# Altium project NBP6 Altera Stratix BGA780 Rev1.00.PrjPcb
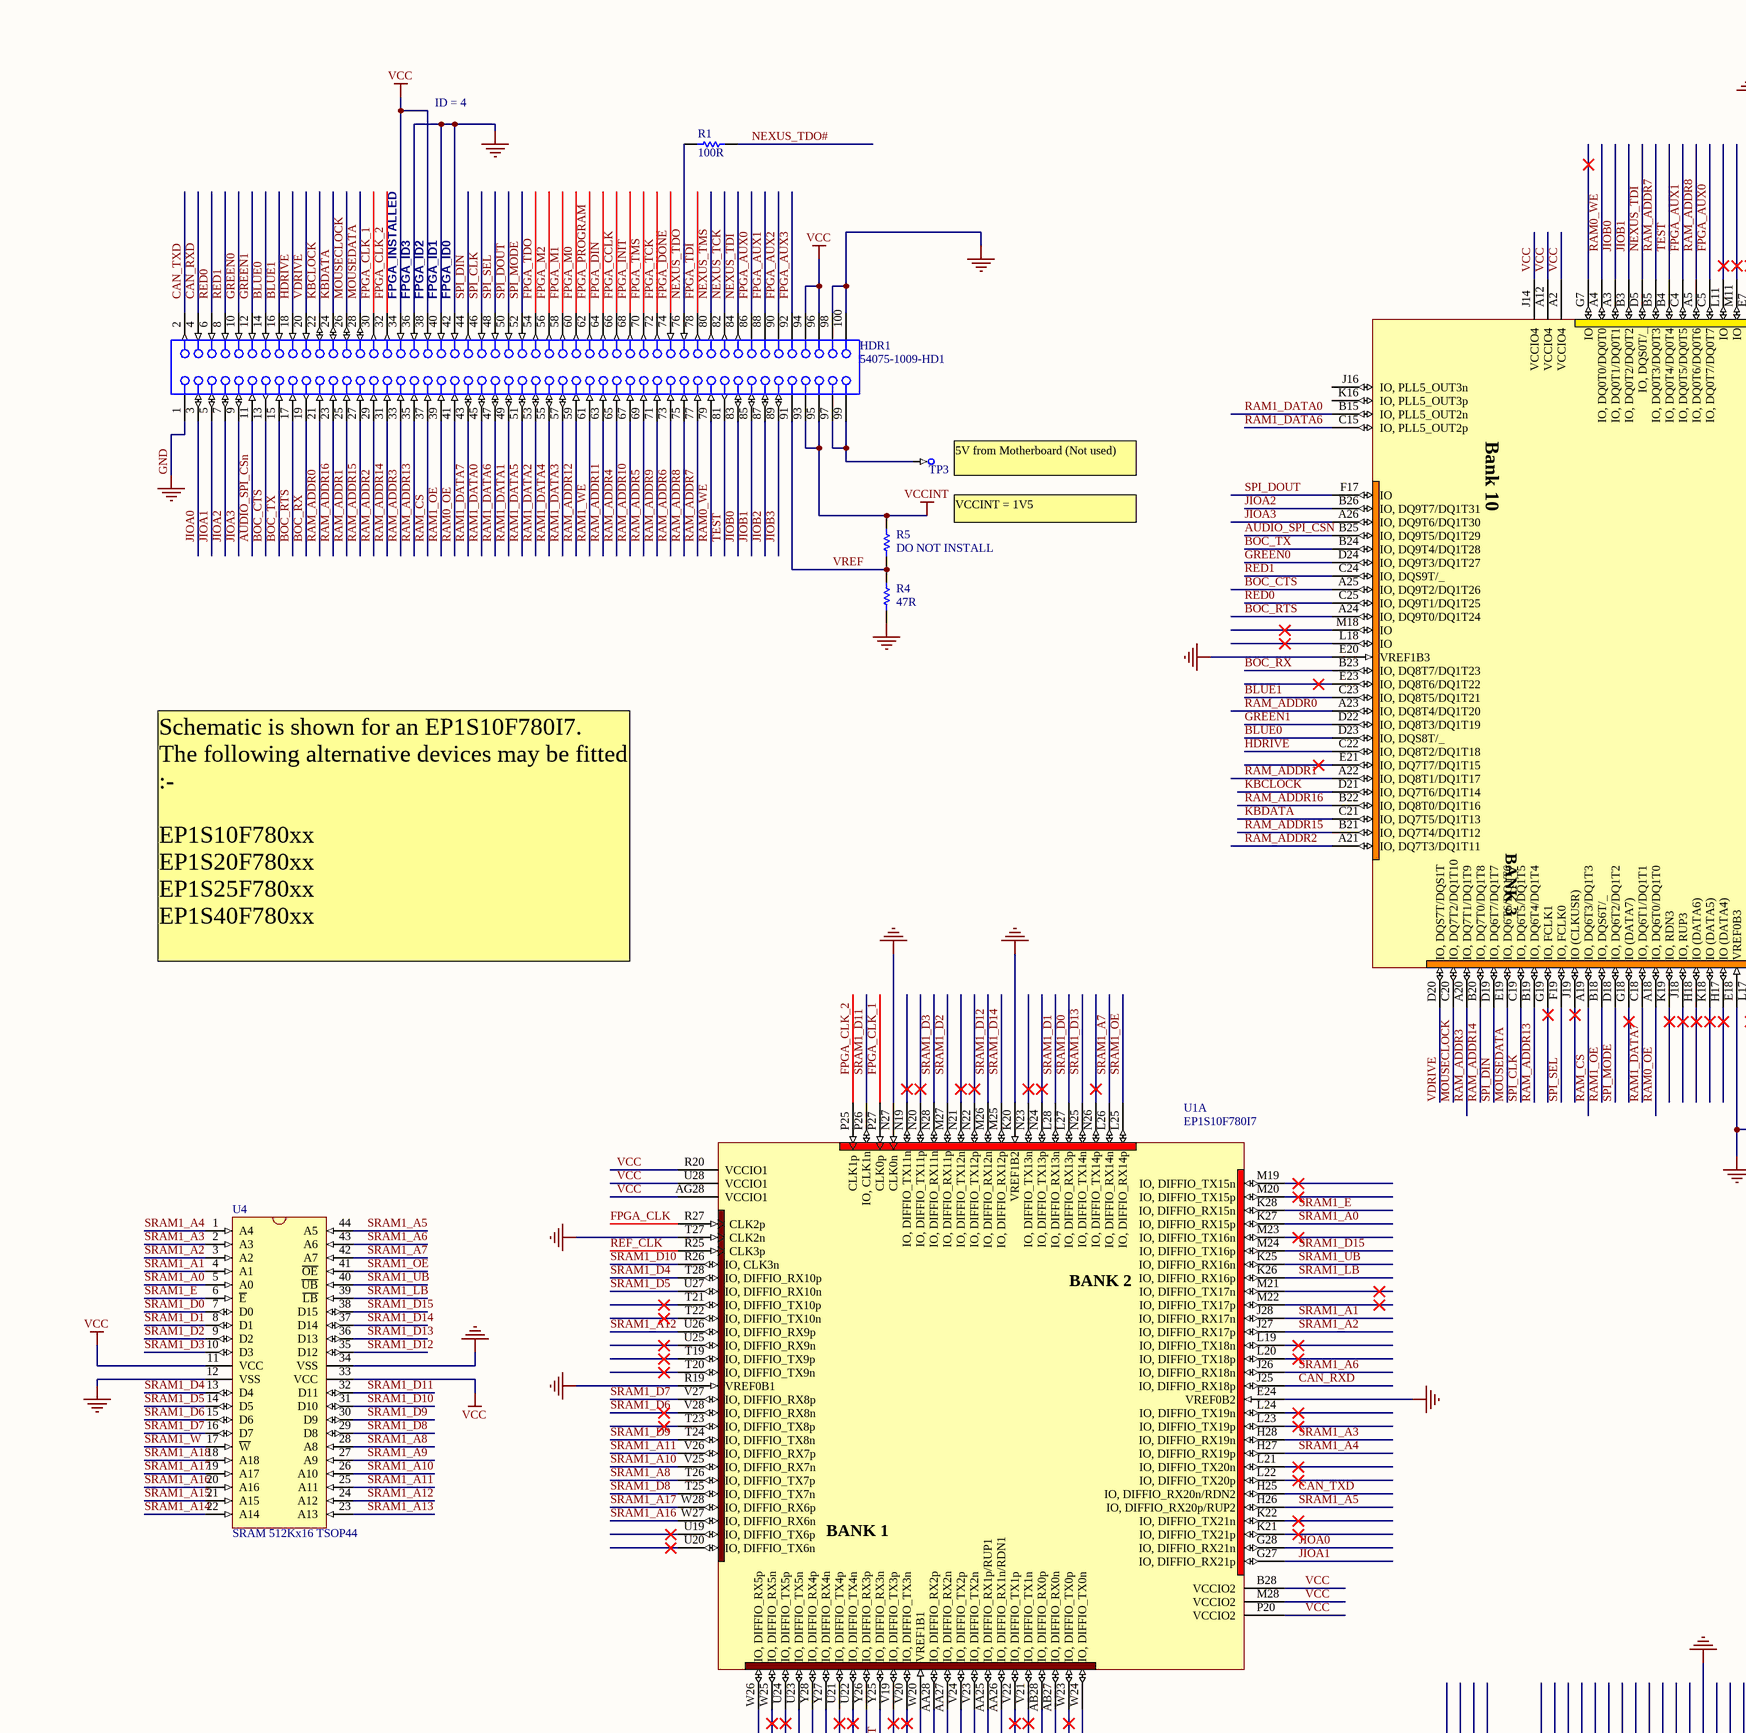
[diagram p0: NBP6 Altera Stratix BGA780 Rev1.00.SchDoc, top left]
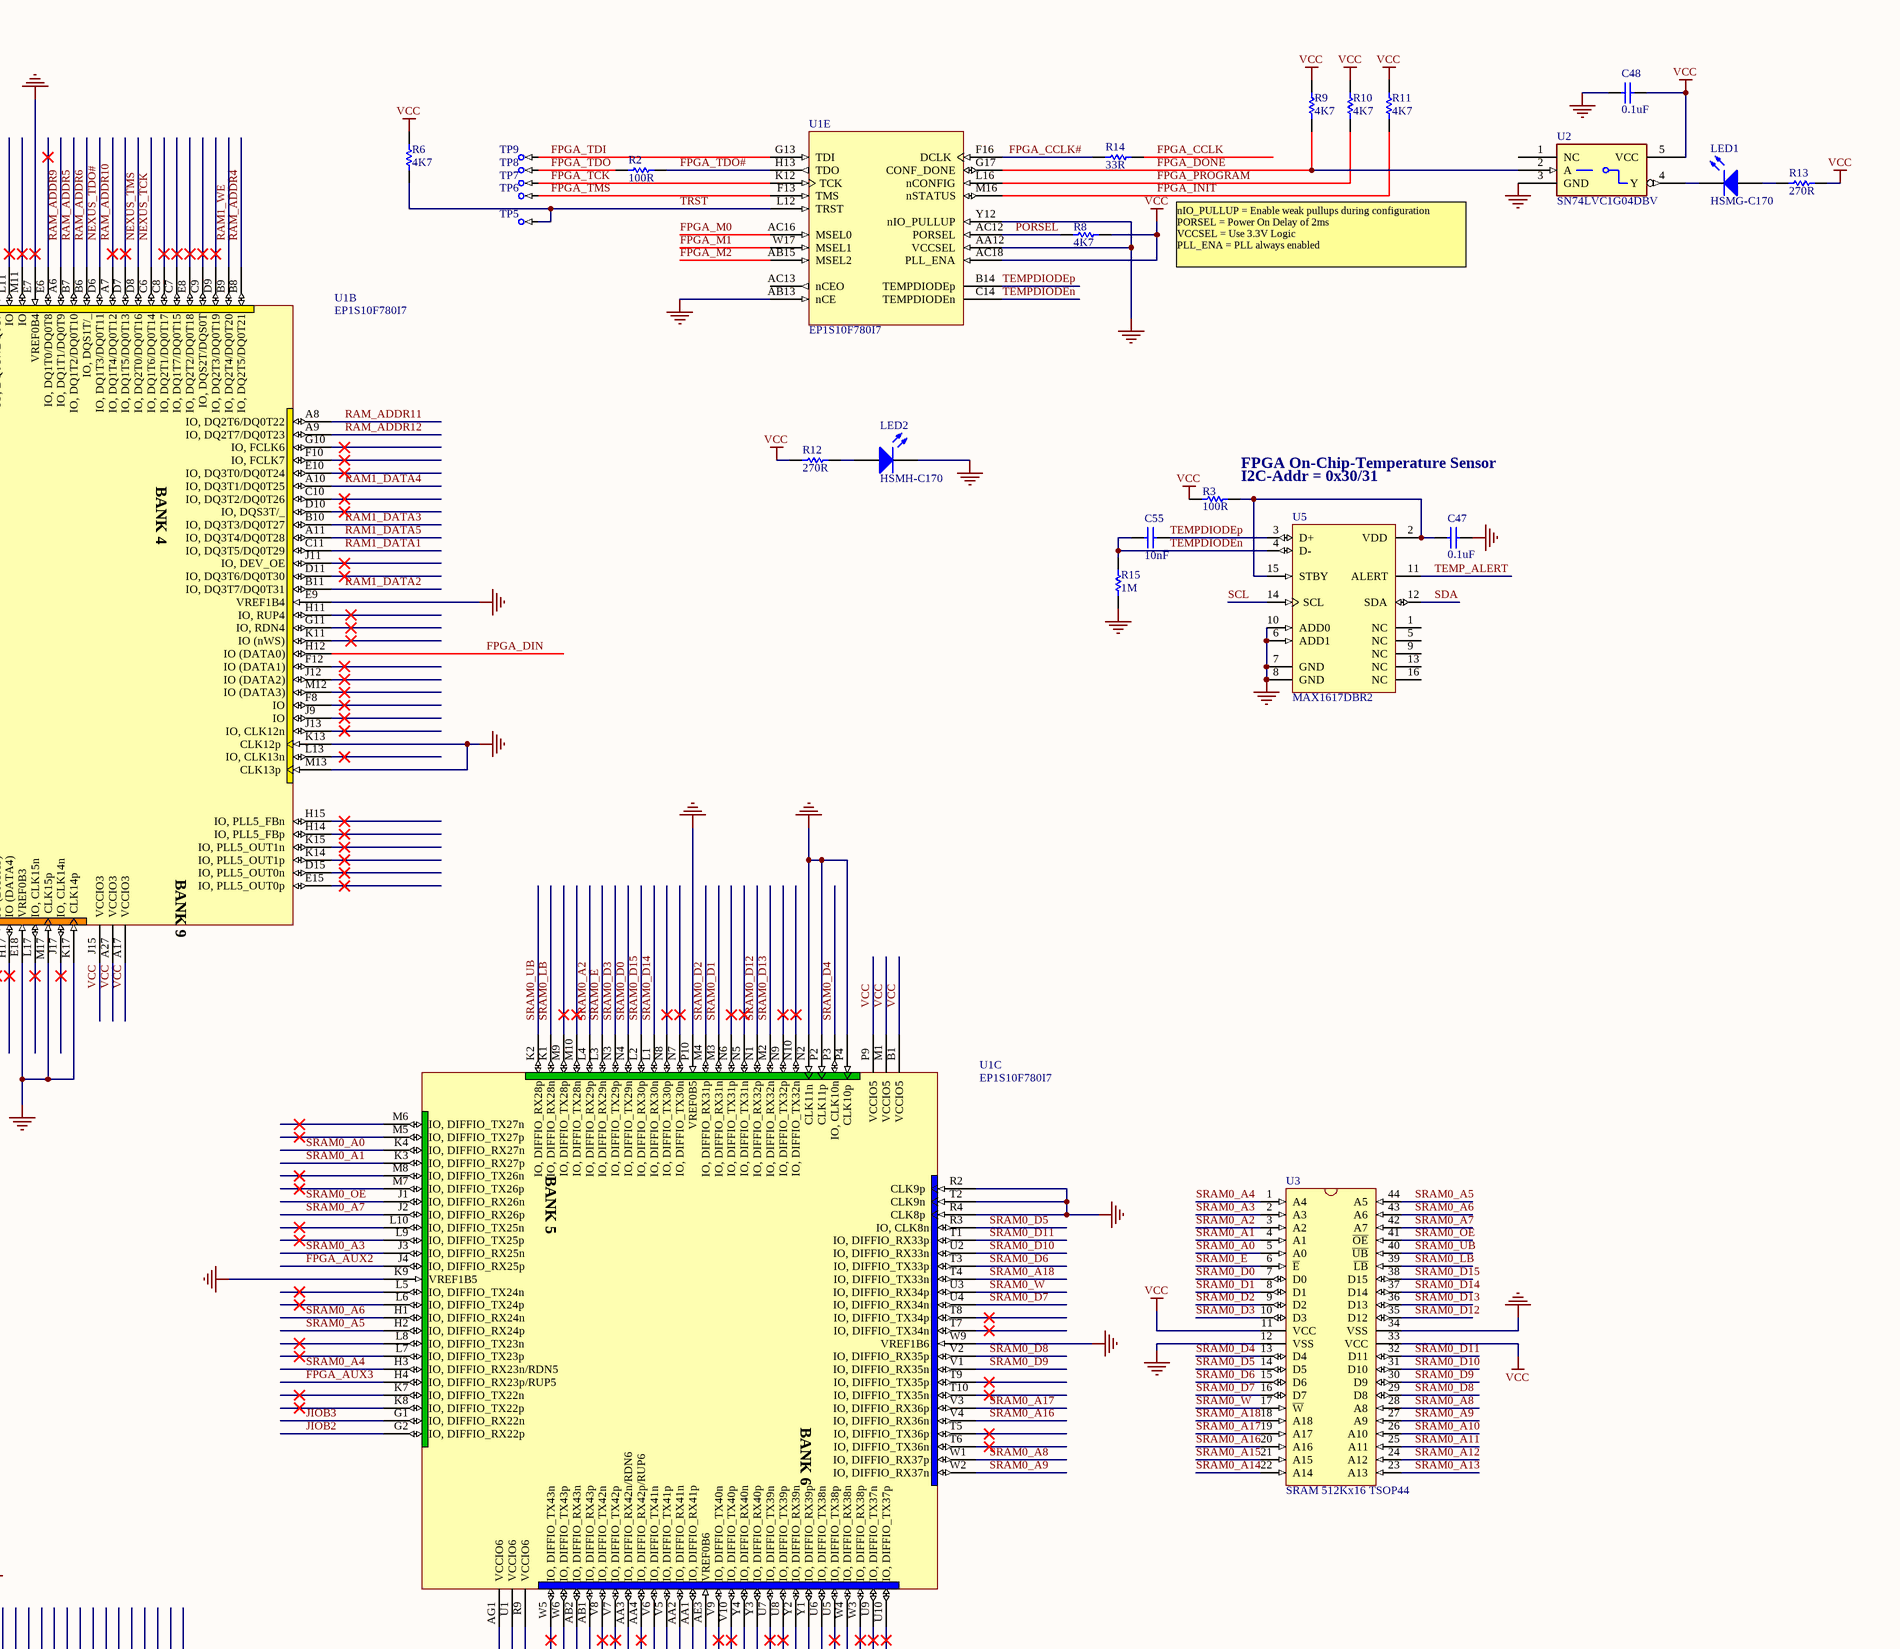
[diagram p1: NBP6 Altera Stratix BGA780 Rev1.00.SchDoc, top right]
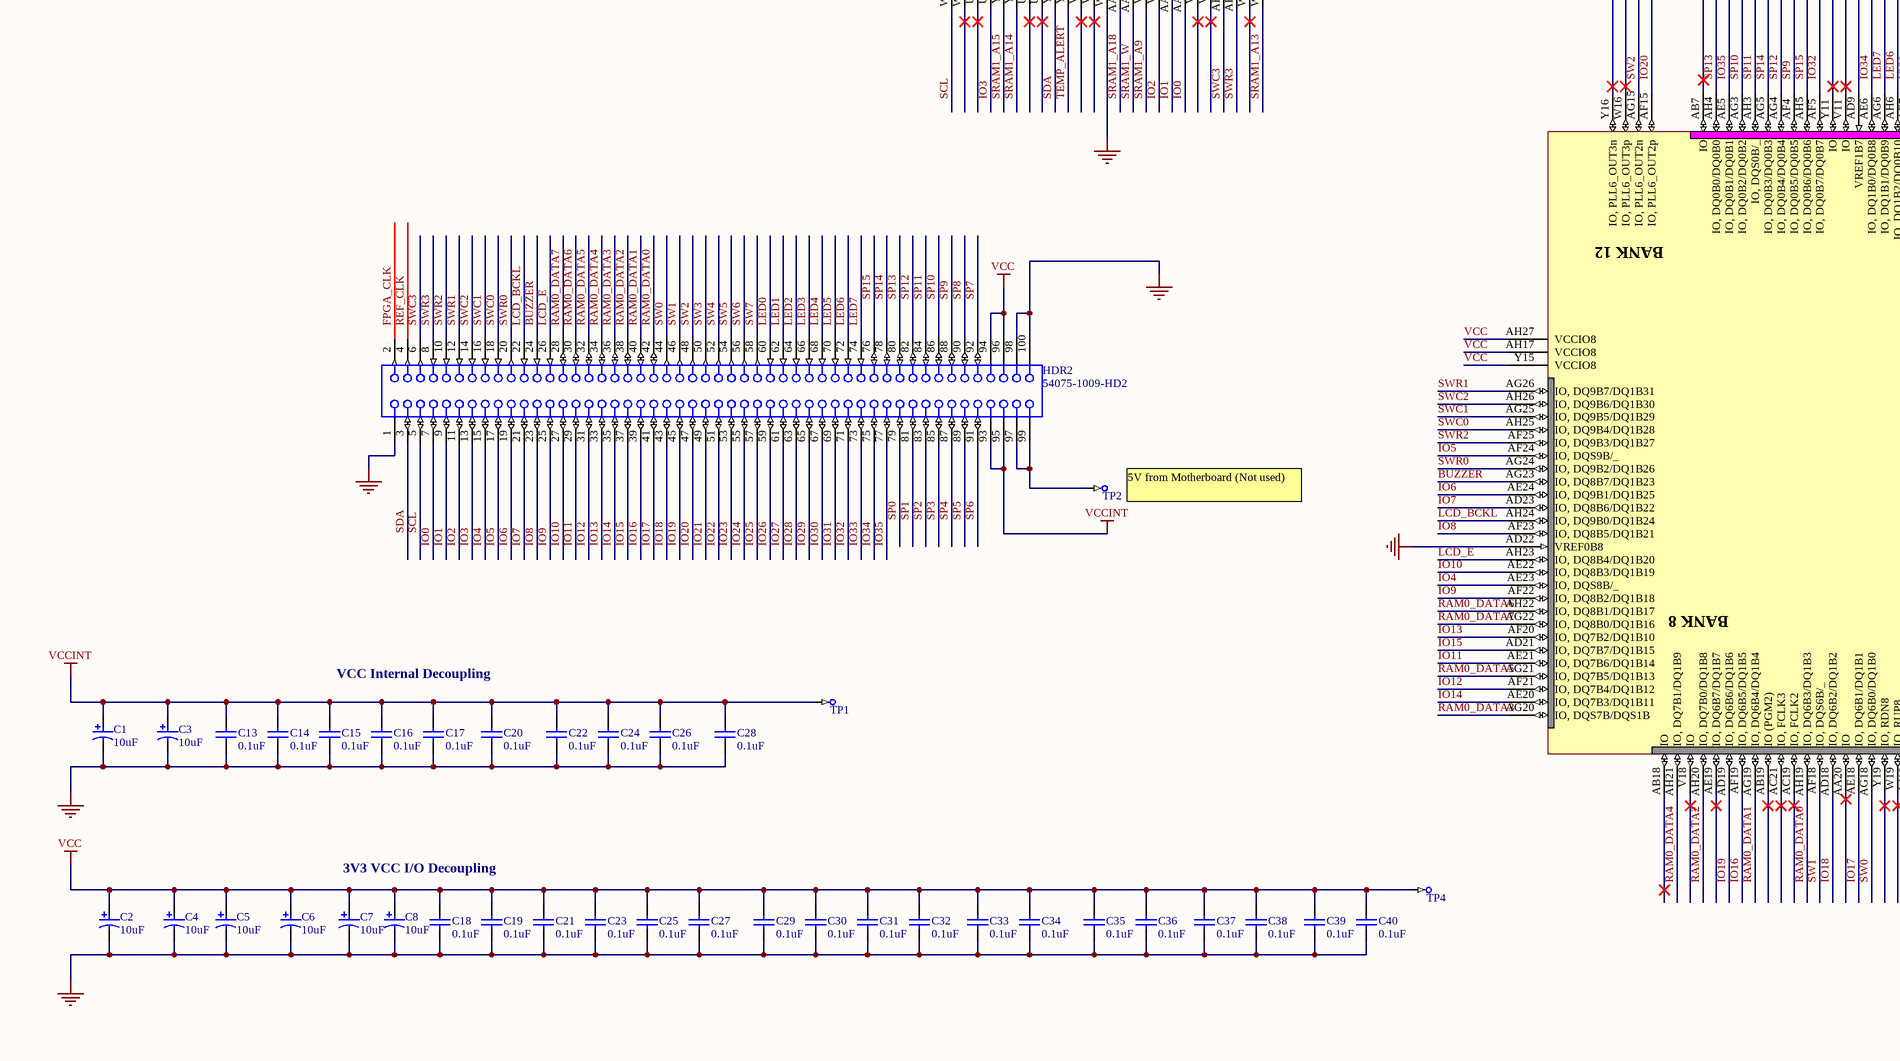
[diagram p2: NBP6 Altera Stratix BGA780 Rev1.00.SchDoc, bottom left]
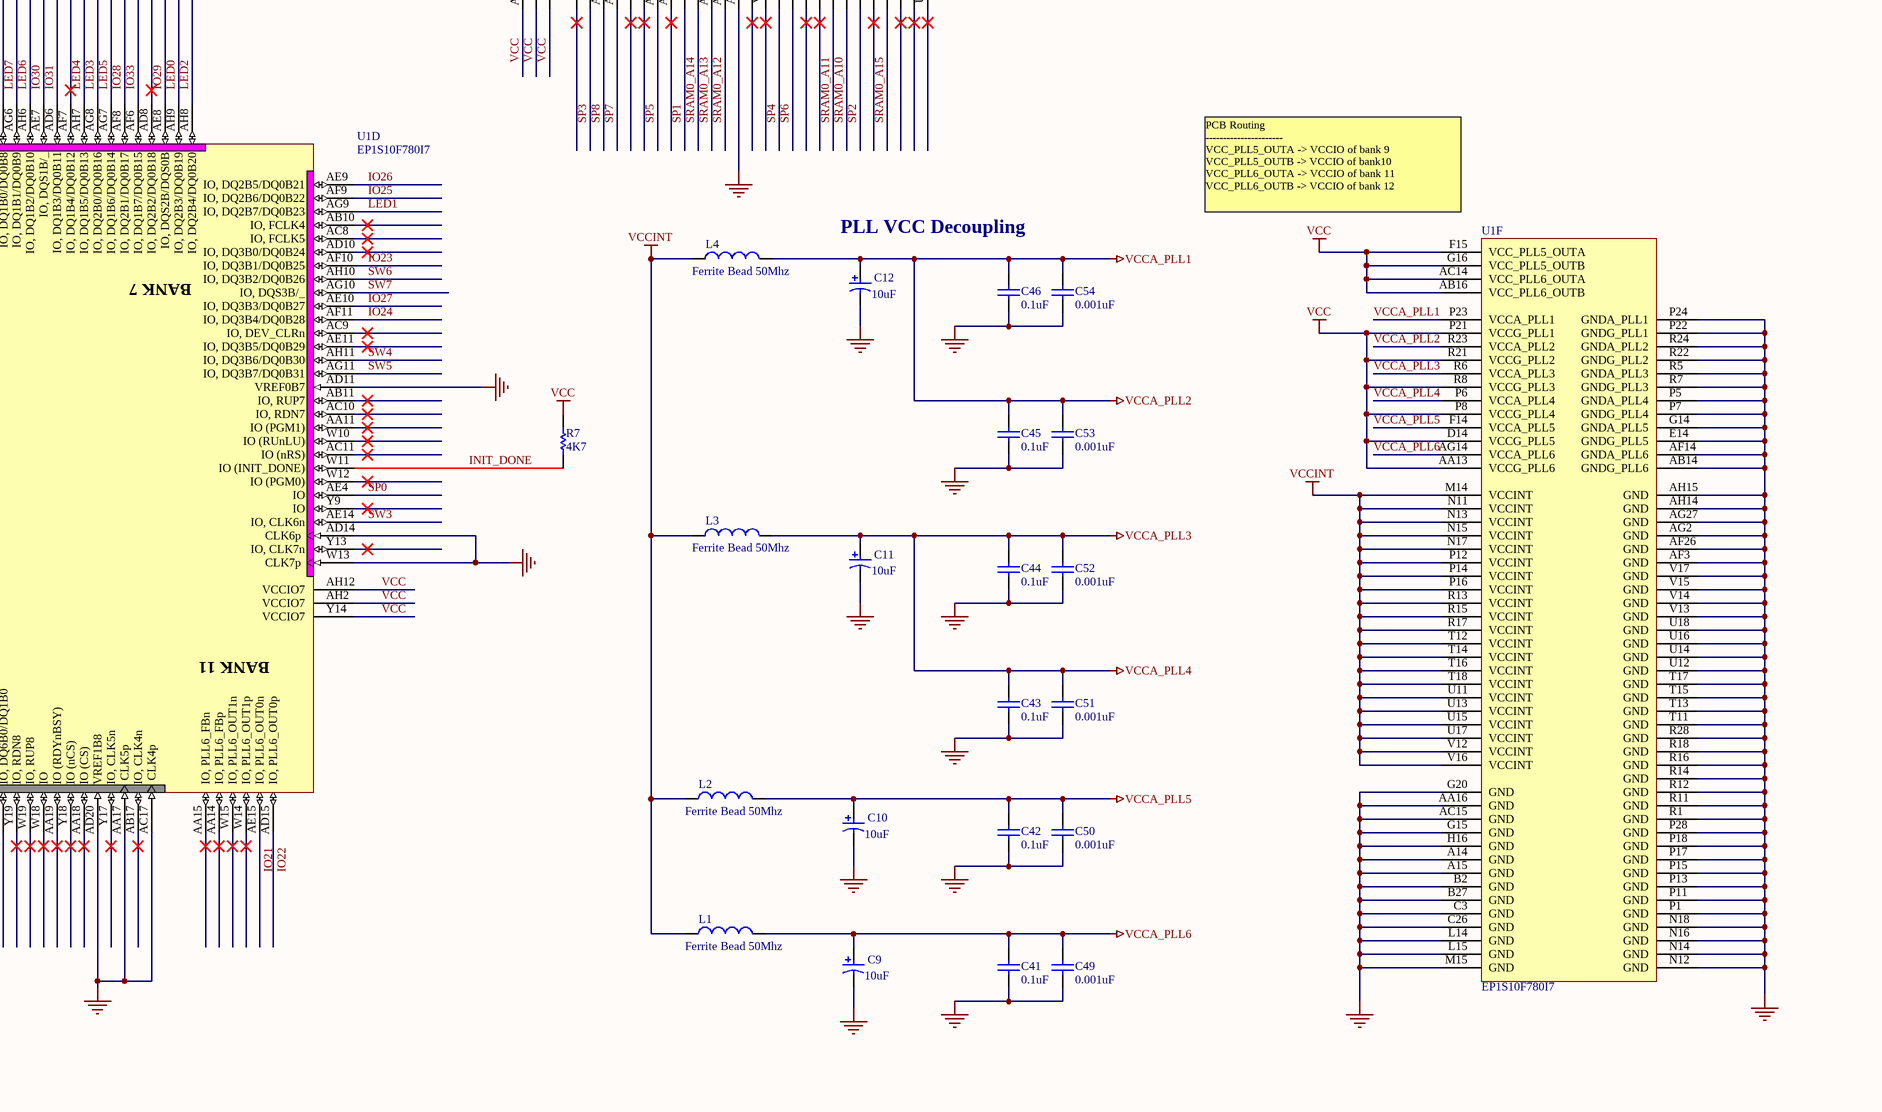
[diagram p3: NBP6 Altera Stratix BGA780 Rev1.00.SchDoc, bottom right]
1 sheet, 92 parts. Net scope: global (net labels, ports and power ports of the same name join across sheets).
Board file: NBP6 Altera Stratix BGA780 Rev1.00.PcbDoc

## Sheet NBP6 Altera Stratix BGA780 Rev1.00.SchDoc: Cyclone EP1C12 Daughterboard
size A1; Organization: Altium Limited; Address1: L3, 12a Rodborough Rd; Address2: Frenchs Forest; Address3: NSW; Address4: Australia 2086; DocumentNumber: 1; Revision: 1.02; SheetNumber: 1; SheetTotal: 1

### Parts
C1  10uF  [MCCT-B]
C2  10uF  [MCCT-B]
C3  10uF  [MCCT-B]
C4  10uF  [MCCT-B]
C5  10uF  [MCCT-B]
C6  10uF  [MCCT-B]
C7  10uF  [MCCT-B]
C8  10uF  [MCCT-B]
C9  10uF  [MCCT-B]
C10  10uF  [MCCT-B]
C11  10uF  [MCCT-B]
C12  10uF  [MCCT-B]
C13  0.1uF  [CC2012-0805]
C14  0.1uF  [CC2012-0805]
C15  0.1uF  [CC2012-0805]
C16  0.1uF  [CC2012-0805]
C17  0.1uF  [CC2012-0805]
C18  0.1uF  [CC2012-0805]
C19  0.1uF  [CC2012-0805]
C20  0.1uF  [CC2012-0805]
C21  0.1uF  [CC2012-0805]
C22  0.1uF  [CC2012-0805]
C23  0.1uF  [CC2012-0805]
C24  0.1uF  [CC2012-0805]
C25  0.1uF  [CC2012-0805]
C26  0.1uF  [CC2012-0805]
C27  0.1uF  [CC2012-0805]
C28  0.1uF  [CC2012-0805]
C29  0.1uF  [CC2012-0805]
C30  0.1uF  [CC2012-0805]
C31  0.1uF  [CC2012-0805]
C32  0.1uF  [CC2012-0805]
C33  0.1uF  [CC2012-0805]
C34  0.1uF  [CC2012-0805]
C35  0.1uF  [CC2012-0805]
C36  0.1uF  [CC2012-0805]
C37  0.1uF  [CC2012-0805]
C38  0.1uF  [CC2012-0805]
C39  0.1uF  [CC2012-0805]
C40  0.1uF  [CC2012-0805]
C41  0.1uF  [CC2012-0805]
C42  0.1uF  [CC2012-0805]
C43  0.1uF  [CC2012-0805]
C44  0.1uF  [CC2012-0805]
C45  0.1uF  [CC2012-0805]
C46  0.1uF  [CC2012-0805]
C47  0.1uF  [CC2012-0805]
C48  0.1uF  [CC2012-0805]
C49  0.001uF  [CC2012-0805]
C50  0.001uF  [CC2012-0805]
C51  0.001uF  [CC2012-0805]
C52  0.001uF  [CC2012-0805]
C53  0.001uF  [CC2012-0805]
C54  0.001uF  [CC2012-0805]
C55  10nF  [CC2012-0805]
HDR1  54075-1009-HD1  [54075]
HDR2  54075-1009-HD2  [54075]
L1  Ferrite Bead 50Mhz  [CC2012-0805]
L2  Ferrite Bead 50Mhz  [CC2012-0805]
L3  Ferrite Bead 50Mhz  [CC2012-0805]
L4  Ferrite Bead 50Mhz  [CC2012-0805]
LED1  HSMG-C170  [SMD _LED]
LED2  HSMH-C170  [SMD _LED]
R1  100R  [CC2012-0805]
R2  100R  [CC2012-0805]
R3  100R  [CC2012-0805]
R4  47R  [CC2012-0805]
R5  DO NOT INSTALL  [CC2012-0805]
R6  4K7  [CC2012-0805]
R7  4K7  [CC2012-0805]
R8  4K7  [CC2012-0805]
R9  4K7  [CC2012-0805]
R10  4K7  [CC2012-0805]
R11  4K7  [CC2012-0805]
R12  270R  [CC2012-0805]
R13  270R  [CC2012-0805]
R14  33R  [CC2012-0805]
R15  1M  [CC2012-0805]
TP1  TestPin  [TestPin]  (value not drawn)  (no BOM)
TP2  TestPin  [TestPin]  (value not drawn)  (no BOM)
TP3  TestPin  [TestPin]  (value not drawn)  (no BOM)
TP4  TestPin  [TestPin]  (value not drawn)  (no BOM)
TP5  TestPin  [TestPin]  (value not drawn)  (no BOM)
TP6  TestPin  [TestPin]  (value not drawn)  (no BOM)
TP7  TestPin  [TestPin]  (value not drawn)  (no BOM)
TP8  TestPin  [TestPin]  (value not drawn)  (no BOM)
TP9  TestPin  [TestPin]  (value not drawn)  (no BOM)
U1  EP1S10F780I7  [FBGA780]  (parts A,B,C,D,E,F of 7)
U2  SN74LVC1G04DBV  [SO-G5/P.95]
U3  SRAM 512Kx16 TSOP44  [SO-G44/P.8]
U4  SRAM 512Kx16 TSOP44  [SO-G44/P.8]
U5  MAX1617DBR2  [QSOP16]

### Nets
GND: C1.2 C2.2 C3.2 C4.2 C5.2 C6.2 C7.2 C8.2 C9.2 C10.2 C11.2 C12.2 C13.2 C14.2 C15.2 C16.2 C17.2 C18.2 C19.2 C20.2 C21.2 C22.2 C23.2 C24.2 C25.2 C26.2 C27.2 C28.2 C29.2 C30.2 C31.2 C32.2 C33.2 C34.2 C35.2 C36.2 C37.2 C38.2 C39.2 C40.2 C41.2 C42.2 C43.2 C44.2 C45.2 C46.2 C47.2 C48.2 C49.2 C50.2 C51.2 C52.2 C53.2 C54.2 HDR1.1 HDR1.36 HDR1.40 HDR1.42 HDR1.98 HDR1.100 HDR2.1 HDR2.98 HDR2.100 LED2.2(K) R4.2 R15.1 U1.A14(GND) U1.A15(GND) U1.AA12(VCCSEL) U1.AA16(GND) U1.AA17(CLK5p) U1.AB13(nCE) U1.AB14(GNDG_PLL6) U1.AC15(GND) U1.AC17(CLK4p) U1.AD9(VREF1B7) U1.AD11(VREF0B7) U1.AD14(CLK6p) U1.AD20(VREF1B8) U1.AD22(VREF0B8) U1.AE3(VREF0B6) U1.AF3(GND) U1.AF14(GNDA_PLL6) U1.AF26(GND) U1.AG2(GND) U1.AG27(GND) U1.AH14(GND) U1.AH15(GND) U1.B2(GND) U1.B27(GND) U1.C3(GND) U1.C26(GND) U1.E7(VREF0B4) U1.E9(VREF1B4) U1.E14(GNDG_PLL5) U1.E18(VREF0B3) U1.E20(VREF1B3) U1.E24(VREF0B2) U1.G14(GNDA_PLL5) U1.G15(GND) U1.G20(GND) U1.H16(GND) U1.K9(VREF1B5) U1.K13(CLK12p) U1.K17(CLK14p) U1.K20(VREF1B2) U1.L14(GND) U1.L15(GND) U1.M13(CLK13p) U1.M15(GND) U1.M17(CLK15p) U1.N2(CLK11n) U1.N12(GND) U1.N14(GND) U1.N16(GND) U1.N18(GND) U1.N27(CLK0n) U1.P1(GND) U1.P2(CLK11p) U1.P4(CLK10p) U1.P5(GNDA_PLL4) U1.P7(GNDG_PLL4) U1.P10(VREF0B5) U1.P11(GND) U1.P13(GND) U1.P15(GND) U1.P17(GND) U1.P18(GND) U1.P22(GNDG_PLL1) U1.P24(GNDA_PLL1) U1.P28(GND) U1.R1(GND) U1.R2(CLK9p) U1.R4(CLK8p) U1.R5(GNDA_PLL3) U1.R7(GNDG_PLL3) U1.R11(GND) U1.R12(GND) U1.R14(GND) U1.R16(GND) U1.R18(GND) U1.R19(VREF0B1) U1.R22(GNDG_PLL2) U1.R24(GNDA_PLL2) U1.R28(GND) U1.T2(CLK9n) U1.T11(GND) U1.T13(GND) U1.T15(GND) U1.T17(GND) U1.T27(CLK2n) U1.U12(GND) U1.U14(GND) U1.U16(GND) U1.U18(GND) U1.V13(GND) U1.V14(GND) U1.V15(GND) U1.V17(GND) U1.W9(VREF1B6) U1.W13(CLK7p) U1.W20(VREF1B1) U1.Y12(nIO_PULLUP) U2.3(GND) U3.12(VSS) U3.34(VSS) U4.12(VSS) U4.34(VSS) U5.6(ADD1) U5.7(GND) U5.8(GND) U5.10(ADD0)
VCC: C2.1 C4.1 C5.1 C6.1 C7.1 C8.1 C18.1 C19.1 C21.1 C23.1 C25.1 C27.1 C29.1 C30.1 C31.1 C32.1 C33.1 C34.1 C35.1 C36.1 C37.1 C38.1 C39.1 C40.1 C48.1 HDR1.34 HDR1.38 HDR1.94 HDR1.96 HDR2.94 HDR2.96 R3.1 R6.1 R7.1 R8.2 R9.1 R10.1 R11.1 R12.1 R13.1 TP4.1 U1.A2(VCCIO4) U1.A12(VCCIO4) U1.A17(VCCIO3) U1.A27(VCCIO3) U1.AA13(VCCG_PLL6) U1.AB16(VCC_PLL6_OUTB) U1.AC14(VCC_PLL6_OUTA) U1.AC18(PLL_ENA) U1.AG1(VCCIO6) U1.AG28(VCCIO1) U1.AH2(VCCIO7) U1.AH12(VCCIO7) U1.AH17(VCCIO8) U1.AH27(VCCIO8) U1.B1(VCCIO5) U1.B28(VCCIO2) U1.D14(VCCG_PLL5) U1.F15(VCC_PLL5_OUTA) U1.G16(VCC_PLL5_OUTB) U1.J14(VCCIO4) U1.J15(VCCIO3) U1.M1(VCCIO5) U1.M28(VCCIO2) U1.P8(VCCG_PLL4) U1.P9(VCCIO5) U1.P20(VCCIO2) U1.P21(VCCG_PLL1) U1.R8(VCCG_PLL3) U1.R9(VCCIO6) U1.R20(VCCIO1) U1.R21(VCCG_PLL2) U1.U1(VCCIO6) U1.U28(VCCIO1) U1.Y14(VCCIO7) U1.Y15(VCCIO8) U2.5(VCC) U3.11(VCC) U3.33(VCC) U4.11(VCC) U4.33(VCC)
VCCA_PLL1: C12.1 C45.1 C46.1 C53.1 C54.1 L4.2 U1.P23(VCCA_PLL1) U1.R23(VCCA_PLL2)  [also labelled VCCA_PLL2]
VCCA_PLL3: C11.1 C43.1 C44.1 C51.1 C52.1 L3.2 U1.P6(VCCA_PLL4) U1.R6(VCCA_PLL3)  [also labelled VCCA_PLL4]
VCCA_PLL5: C10.1 C42.1 C50.1 L2.2 U1.F14(VCCA_PLL5)
VCCA_PLL6: C9.1 C41.1 C49.1 L1.2 U1.AG14(VCCA_PLL6)
VCCINT: C1.1 C3.1 C13.1 C14.1 C15.1 C16.1 C17.1 C20.1 C22.1 C24.1 C26.1 C28.1 HDR1.93 HDR1.95 HDR2.93 HDR2.95 L1.1 L2.1 L3.1 L4.1 R5.1 TP1.1 U1.M14(VCCINT) U1.N11(VCCINT) U1.N13(VCCINT) U1.N15(VCCINT) U1.N17(VCCINT) U1.P12(VCCINT) U1.P14(VCCINT) U1.P16(VCCINT) U1.R13(VCCINT) U1.R15(VCCINT) U1.R17(VCCINT) U1.T12(VCCINT) U1.T14(VCCINT) U1.T16(VCCINT) U1.T18(VCCINT) U1.U11(VCCINT) U1.U13(VCCINT) U1.U15(VCCINT) U1.U17(VCCINT) U1.V12(VCCINT) U1.V16(VCCINT)
AUDIO_SPI_CSn: HDR1.11 U1.B25(IO,_DQ9T5/DQ1T29)
BLUE0: HDR1.14 U1.D23(IO,_DQS8T/_)
BLUE1: HDR1.16 U1.C23(IO,_DQ8T5/DQ1T21)
BOC_CTS: HDR1.13 U1.A25(IO,_DQ9T2/DQ1T26)
BOC_RTS: HDR1.17 U1.A24(IO,_DQ9T0/DQ1T24)
BOC_RX: HDR1.19 U1.B23(IO,_DQ8T7/DQ1T23)
BOC_TX: HDR1.15 U1.B24(IO,_DQ9T4/DQ1T28)
BUZZER: HDR2.24 U1.AG23(IO,_DQ8B7/DQ1B23)
CAN_RXD: HDR1.4 U1.J25(IO,_DIFFIO_RX18p)
CAN_TXD: HDR1.2 U1.H25(IO,_DIFFIO_RX20n/RDN2)
FPGA_AUX0: HDR1.86 U1.C5(IO,_DQ0T7/DQ0T7)
FPGA_AUX1: HDR1.88 U1.C4(IO,_DQ0T5/DQ0T5)
FPGA_AUX2: HDR1.90 U1.J4(IO,_DIFFIO_RX25p)
FPGA_AUX3: HDR1.92 U1.H4(IO,_DIFFIO_RX23p/RUP5)
FPGA_CCLK: HDR1.66 R14.2
FPGA_CCLK#: R14.1 U1.F16(DCLK)
FPGA_CLK: HDR2.2 U1.R27(CLK2p)
FPGA_CLK_1: HDR1.30 U1.P27(CLK0p)
FPGA_CLK_2: HDR1.32 U1.P25(CLK1p)
FPGA_DIN: HDR1.64 U1.H12(IO_(DATA0))
FPGA_DONE: HDR1.74 R9.2 U1.G17(CONF_DONE) U2.2(A)
FPGA_INIT: HDR1.68 R11.2 U1.M16(nSTATUS)
FPGA_M0: HDR1.60 U1.AC16(MSEL0)
FPGA_M1: HDR1.58 U1.W17(MSEL1)
FPGA_M2: HDR1.56 U1.AB15(MSEL2)
FPGA_PROGRAM: HDR1.62 R10.2 U1.L16(nCONFIG)
FPGA_TCK: HDR1.72 TP7.1 U1.K12(TCK)
FPGA_TDI: HDR1.78 TP9.1 U1.G13(TDI)
FPGA_TDO: HDR1.54 R2.1 TP8.1
FPGA_TDO#: R2.2 U1.H13(TDO)
FPGA_TMS: HDR1.70 TP6.1 U1.F13(TMS)
GREEN0: HDR1.10 U1.D24(IO,_DQ9T3/DQ1T27)
GREEN1: HDR1.12 U1.D22(IO,_DQ8T3/DQ1T19)
HDRIVE: HDR1.18 U1.C22(IO,_DQ8T2/DQ1T18)
INIT_DONE: R7.2 U1.W11(IO_(INIT_DONE))
IO0: HDR2.7 U1.AA26(IO,_DIFFIO_RX1n/RDN1)
IO1: HDR2.9 U1.AA25(IO,_DIFFIO_RX1p/RUP1)
IO2: HDR2.11 U1.V23(IO,_DIFFIO_TX2n)
IO3: HDR2.13 U1.U23(IO,_DIFFIO_TX5n)
IO4: HDR2.15 U1.AE23(IO,_DQS8B/_)
IO5: HDR2.17 U1.AF24(IO,_DQS9B/_)
IO6: HDR2.19 U1.AE24(IO,_DQ9B1/DQ1B25)
IO7: HDR2.21 U1.AD23(IO,_DQ8B6/DQ1B22)
IO8: HDR2.23 U1.AF23(IO,_DQ8B5/DQ1B21)
IO9: HDR2.25 U1.AF22(IO,_DQ8B2/DQ1B18)
IO10: HDR2.27 U1.AE22(IO,_DQ8B3/DQ1B19)
IO11: HDR2.29 U1.AE21(IO,_DQ7B6/DQ1B14)
IO12: HDR2.31 U1.AF21(IO,_DQ7B4/DQ1B12)
IO13: HDR2.33 U1.AF20(IO,_DQ7B2/DQ1B10)
IO14: HDR2.35 U1.AE20(IO,_DQ7B3/DQ1B11)
IO15: HDR2.37 U1.AD21(IO,_DQ7B7/DQ1B15)
IO16: HDR2.39 U1.AF19(IO,_DQ6B5/DQ1B5)
IO17: HDR2.41 U1.AE18(IO,_DQ6B1/DQ1B1)
IO18: HDR2.43 U1.AD18(IO,_DQ6B2/DQ1B2)
IO19: HDR2.45 U1.AD19(IO,_DQ6B6/DQ1B6)
IO20: HDR2.47 U1.AF15(IO,_PLL6_OUT2p)
IO21: HDR2.49 U1.AE15(IO,_PLL6_OUT0n)
IO22: HDR2.51 U1.AD15(IO,_PLL6_OUT0p)
IO23: HDR2.53 U1.AF10(IO,_DQ3B1/DQ0B25)
IO24: HDR2.55 U1.AF11(IO,_DQ3B4/DQ0B28)
IO25: HDR2.57 U1.AF9(IO,_DQ2B6/DQ0B22)
IO26: HDR2.59 U1.AE9(IO,_DQ2B5/DQ0B21)
IO27: HDR2.61 U1.AE10(IO,_DQ3B3/DQ0B27)
IO28: HDR2.63 U1.AF8(IO,_DQ2B1/DQ0B17)
IO29: HDR2.65 U1.AE8(IO,_DQS2B/DQS0B)
IO30: HDR2.67 U1.AE7(IO,_DQS1B/_)
IO31: HDR2.69 U1.AD6(IO,_DQ1B3/DQ0B11)
IO32: HDR2.71 U1.AF5(IO,_DQ0B7/DQ0B7)
IO33: HDR2.73 U1.AF6(IO,_DQ1B7/DQ0B15)
IO34: HDR2.75 U1.AE6(IO,_DQ1B0/DQ0B8)
IO35: HDR2.77 U1.AE5(IO,_DQ0B1/DQ0B1)
JIOA0: HDR1.3 U1.G28(IO,_DIFFIO_RX21n)
JIOA1: HDR1.5 U1.G27(IO,_DIFFIO_RX21p)
JIOA2: HDR1.7 U1.B26(IO,_DQ9T7/DQ1T31)
JIOA3: HDR1.9 U1.A26(IO,_DQ9T6/DQ1T30)
JIOB0: HDR1.83 U1.A3(IO,_DQ0T1/DQ0T1)
JIOB1: HDR1.85 U1.B3(IO,_DQ0T2/DQ0T2)
JIOB2: HDR1.87 U1.G2(IO,_DIFFIO_RX22p)
JIOB3: HDR1.89 U1.G1(IO,_DIFFIO_RX22n)
KBCLOCK: HDR1.22 U1.D21(IO,_DQ7T6/DQ1T14)
KBDATA: HDR1.24 U1.C21(IO,_DQ7T5/DQ1T13)
LCD_BCKL: HDR2.22 U1.AH24(IO,_DQ9B0/DQ1B24)
LCD_E: HDR2.26 U1.AH23(IO,_DQ8B4/DQ1B20)
LED0: HDR2.60 U1.AH9(IO,_DQ2B3/DQ0B19)
LED1: HDR2.62 U1.AG9(IO,_DQ2B7/DQ0B23)
LED2: HDR2.64 U1.AH8(IO,_DQ2B4/DQ0B20)
LED3: HDR2.66 U1.AG8(IO,_DQ2B0/DQ0B16)
LED4: HDR2.68 U1.AH7(IO,_DQ1B5/DQ0B13)
LED5: HDR2.70 U1.AG7(IO,_DQ1B6/DQ0B14)
LED6: HDR2.72 U1.AH6(IO,_DQ1B2/DQ0B10)
LED7: HDR2.74 U1.AG6(IO,_DQ1B1/DQ0B9)
MOUSECLOCK: HDR1.26 U1.C20(IO,_DQ7T2/DQ1T10)
MOUSEDATA: HDR1.28 U1.E19(IO,_DQ6T6/DQ1T6)
NEXUS_TCK: HDR1.82 U1.C6(IO,_DQ1T6/DQ0T14)
NEXUS_TDI: HDR1.84 U1.D5(IO,_DQS0T/_)
NEXUS_TDO: HDR1.76 R1.1
NEXUS_TDO#: R1.2 U1.D6(IO,_DQ1T3/DQ0T11)
NEXUS_TMS: HDR1.80 U1.D8(IO,_DQ2T0/DQ0T16)
PORSEL: R8.1 U1.AC12(PORSEL)
RAM0_DATA0: HDR2.42 U1.AH19(IO,_DQ6B3/DQ1B3)
RAM0_DATA1: HDR2.40 U1.AG19(IO,_DQ6B4/DQ1B4)
RAM0_DATA2: HDR2.38 U1.AH20(IO,_DQ7B0/DQ1B8)
RAM0_DATA3: HDR2.36 U1.AG20(IO,_DQS7B/DQS1B)
RAM0_DATA4: HDR2.34 U1.AH21(IO,_DQ7B1/DQ1B9)
RAM0_DATA5: HDR2.32 U1.AG21(IO,_DQ7B5/DQ1B13)
RAM0_DATA6: HDR2.30 U1.AH22(IO,_DQ8B1/DQ1B17)
RAM0_DATA7: HDR2.28 U1.AG22(IO,_DQ8B0/DQ1B16)
RAM0_OE: HDR1.41 U1.A18(IO,_DQ6T0/DQ1T0)
RAM0_WE: HDR1.79 U1.A4(IO,_DQ0T0/DQ0T0)
RAM1_DATA0: HDR1.45 U1.B15(IO,_PLL5_OUT2n)
RAM1_DATA1: HDR1.49 U1.C11(IO,_DQ3T5/DQ0T29)
RAM1_DATA2: HDR1.53 U1.B11(IO,_DQ3T7/DQ0T31)
RAM1_DATA3: HDR1.57 U1.B10(IO,_DQ3T3/DQ0T27)
RAM1_DATA4: HDR1.55 U1.A10(IO,_DQ3T1/DQ0T25)
RAM1_DATA5: HDR1.51 U1.A11(IO,_DQ3T4/DQ0T28)
RAM1_DATA6: HDR1.47 U1.C15(IO,_PLL5_OUT2p)
RAM1_DATA7: HDR1.43 U1.C18(IO,_DQ6T1/DQ1T1)
RAM1_OE: HDR1.39 U1.B18(IO,_DQS6T/_)
RAM1_WE: HDR1.61 U1.B9(IO,_DQ2T4/DQ0T20)
RAM_ADDR0: HDR1.21 U1.A23(IO,_DQ8T4/DQ1T20)
RAM_ADDR1: HDR1.25 U1.A22(IO,_DQ8T1/DQ1T17)
RAM_ADDR2: HDR1.29 U1.A21(IO,_DQ7T3/DQ1T11)
RAM_ADDR3: HDR1.33 U1.A20(IO,_DQ7T1/DQ1T9)
RAM_ADDR4: HDR1.65 U1.B8(IO,_DQ2T5/DQ0T21)
RAM_ADDR5: HDR1.69 U1.B7(IO,_DQ1T2/DQ0T10)
RAM_ADDR6: HDR1.73 U1.B6(IO,_DQS1T/_)
RAM_ADDR7: HDR1.77 U1.B5(IO,_DQ0T3/DQ0T3)
RAM_ADDR8: HDR1.75 U1.A5(IO,_DQ0T6/DQ0T6)
RAM_ADDR9: HDR1.71 U1.A6(IO,_DQ1T1/DQ0T9)
RAM_ADDR10: HDR1.67 U1.A7(IO,_DQ1T4/DQ0T12)
RAM_ADDR11: HDR1.63 U1.A8(IO,_DQ2T6/DQ0T22)
RAM_ADDR12: HDR1.59 U1.A9(IO,_DQ2T7/DQ0T23)
RAM_ADDR13: HDR1.35 U1.B19(IO,_DQ6T4/DQ1T4)
RAM_ADDR14: HDR1.31 U1.B20(IO,_DQ7T0/DQ1T8)
RAM_ADDR15: HDR1.27 U1.B21(IO,_DQ7T4/DQ1T12)
RAM_ADDR16: HDR1.23 U1.B22(IO,_DQ8T0/DQ1T16)
RAM_CS: HDR1.37 U1.A19(IO,_DQ6T3/DQ1T3)
RED0: HDR1.6 U1.C25(IO,_DQ9T1/DQ1T25)
RED1: HDR1.8 U1.C24(IO,_DQS9T/_)
REF_CLK: HDR2.4 U1.R25(CLK3p)
SCL: HDR2.5 U1.W26(IO,_DIFFIO_RX5p) U5.14(SCL)
SDA: HDR2.3 U1.Y26(IO,_DIFFIO_RX3p) U5.12(SDA)
SP0: HDR2.79 U1.AE4(IO)
SP1: HDR2.81 U1.V6(IO,_DIFFIO_TX41n)
SP2: HDR2.83 U1.U6(IO,_DIFFIO_TX38n)
SP3: HDR2.85 U1.W6(IO,_DIFFIO_TX43p)
SP4: HDR2.87 U1.Y4(IO,_DIFFIO_RX40n)
SP5: HDR2.89 U1.AA3(IO,_DIFFIO_RX42n/RDN6)
SP6: HDR2.91 U1.Y3(IO,_DIFFIO_RX40p)
SP7: HDR2.92 U1.AB1(IO,_DIFFIO_RX43p)
SP8: HDR2.90 U1.AB2(IO,_DIFFIO_RX43n)
SP9: HDR2.88 U1.AF4(IO,_DQ0B5/DQ0B5)
SP10: HDR2.86 U1.AG3(IO,_DQ0B2/DQ0B2)
SP11: HDR2.84 U1.AH3(IO,_DQS0B/_)
SP12: HDR2.82 U1.AG4(IO,_DQ0B4/DQ0B4)
SP13: HDR2.80 U1.AH4(IO,_DQ0B0/DQ0B0)
SP14: HDR2.78 U1.AG5(IO,_DQ0B3/DQ0B3)
SP15: HDR2.76 U1.AH5(IO,_DQ0B6/DQ0B6)
SPI_CLK: HDR1.46 U1.C19(IO,_DQ6T5/DQ1T5)
SPI_DIN: HDR1.44 U1.D19(IO,_DQ6T7/DQ1T7)
SPI_DOUT: HDR1.50 U1.F17(IO)
SPI_MODE: HDR1.52 U1.D18(IO,_DQ6T2/DQ1T2)
SPI_SEL: HDR1.48 U1.F19(IO,_FCLK0)
SRAM0_A0: U1.K4(IO,_DIFFIO_RX27n) U3.5(A0)
SRAM0_A1: U1.K3(IO,_DIFFIO_RX27p) U3.4(A1)
SRAM0_A2: U1.L4(IO,_DIFFIO_RX29p) U3.3(A2)
SRAM0_A3: U1.J3(IO,_DIFFIO_RX25n) U3.2(A3)
SRAM0_A4: U1.H3(IO,_DIFFIO_RX23n/RDN5) U3.1(A4)
SRAM0_A5: U1.H2(IO,_DIFFIO_RX24p) U3.44(A5)
SRAM0_A6: U1.H1(IO,_DIFFIO_RX24n) U3.43(A6)
SRAM0_A7: U1.J2(IO,_DIFFIO_RX26p) U3.42(A7)
SRAM0_A8: U1.W1(IO,_DIFFIO_RX37p) U3.28(A8)
SRAM0_A9: U1.W2(IO,_DIFFIO_RX37n) U3.27(A9)
SRAM0_A10: U1.Y1(IO,_DIFFIO_RX39p) U3.26(A10)
SRAM0_A11: U1.Y2(IO,_DIFFIO_RX39n) U3.25(A11)
SRAM0_A12: U1.AA1(IO,_DIFFIO_RX41p) U3.24(A12)
SRAM0_A13: U1.AA2(IO,_DIFFIO_RX41n) U3.23(A13)
SRAM0_A14: U1.V5(IO,_DIFFIO_TX41p) U3.22(A14)
SRAM0_A15: U1.W4(IO,_DIFFIO_RX38n) U3.21(A15)
SRAM0_A16: U1.V4(IO,_DIFFIO_RX36n) U3.20(A16)
SRAM0_A17: U1.V3(IO,_DIFFIO_RX36p) U3.19(A17)
SRAM0_A18: U1.T4(IO,_DIFFIO_TX33n) U3.18(A18)
SRAM0_D0: U1.N4(IO,_DIFFIO_TX29n) U3.7(D0)
SRAM0_D1: U1.M3(IO,_DIFFIO_RX31n) U3.8(D1)
SRAM0_D2: U1.M4(IO,_DIFFIO_RX31p) U3.9(D2)
SRAM0_D3: U1.N3(IO,_DIFFIO_TX29p) U3.10(D3)
SRAM0_D4: U1.P3(IO,_CLK10n) U3.13(D4)
SRAM0_D5: U1.R3(IO,_CLK8n) U3.14(D5)
SRAM0_D6: U1.T3(IO,_DIFFIO_TX33p) U3.15(D6)
SRAM0_D7: U1.U4(IO,_DIFFIO_RX34n) U3.16(D7)
SRAM0_D8: U1.V2(IO,_DIFFIO_RX35p) U3.29(D8)
SRAM0_D9: U1.V1(IO,_DIFFIO_RX35n) U3.30(D9)
SRAM0_D10: U1.U2(IO,_DIFFIO_RX33n) U3.31(D10)
SRAM0_D11: U1.T1(IO,_DIFFIO_RX33p) U3.32(D11)
SRAM0_D12: U1.N1(IO,_DIFFIO_RX32p) U3.35(D12)
SRAM0_D13: U1.M2(IO,_DIFFIO_RX32n) U3.36(D13)
SRAM0_D14: U1.L1(IO,_DIFFIO_RX30n) U3.37(D14)
SRAM0_D15: U1.L2(IO,_DIFFIO_RX30p) U3.38(D15)
SRAM0_E: U1.L3(IO,_DIFFIO_RX29n) U3.6(~{E})
SRAM0_LB: U1.K1(IO,_DIFFIO_RX28n) U3.39(~{LB})
SRAM0_OE: U1.J1(IO,_DIFFIO_RX26n) U3.41(~{OE})
SRAM0_UB: U1.K2(IO,_DIFFIO_RX28p) U3.40(~{UB})
SRAM0_W: U1.U3(IO,_DIFFIO_RX34p) U3.17(~{W})
SRAM1_A0: U1.K27(IO,_DIFFIO_RX15p) U4.5(A0)
SRAM1_A1: U1.J28(IO,_DIFFIO_RX17n) U4.4(A1)
SRAM1_A2: U1.J27(IO,_DIFFIO_RX17p) U4.3(A2)
SRAM1_A3: U1.H28(IO,_DIFFIO_RX19n) U4.2(A3)
SRAM1_A4: U1.H27(IO,_DIFFIO_RX19p) U4.1(A4)
SRAM1_A5: U1.H26(IO,_DIFFIO_RX20p/RUP2) U4.44(A5)
SRAM1_A6: U1.J26(IO,_DIFFIO_RX18n) U4.43(A6)
SRAM1_A7: U1.L26(IO,_DIFFIO_RX14n) U4.42(A7)
SRAM1_A8: U1.T26(IO,_DIFFIO_TX7p) U4.28(A8)
SRAM1_A9: U1.V24(IO,_DIFFIO_TX2p) U4.27(A9)
SRAM1_A10: U1.V25(IO,_DIFFIO_RX7n) U4.26(A10)
SRAM1_A11: U1.V26(IO,_DIFFIO_RX7p) U4.25(A11)
SRAM1_A12: U1.U26(IO,_DIFFIO_RX9p) U4.24(A12)
SRAM1_A13: U1.W24(IO,_DIFFIO_TX0n) U4.23(A13)
SRAM1_A14: U1.Y27(IO,_DIFFIO_RX4n) U4.22(A14)
SRAM1_A15: U1.Y28(IO,_DIFFIO_RX4p) U4.21(A15)
SRAM1_A16: U1.W27(IO,_DIFFIO_RX6n) U4.20(A16)
SRAM1_A17: U1.W28(IO,_DIFFIO_RX6p) U4.19(A17)
SRAM1_A18: U1.AA28(IO,_DIFFIO_RX2p) U4.18(A18)
SRAM1_D0: U1.L27(IO,_DIFFIO_RX13p) U4.7(D0)
SRAM1_D1: U1.L28(IO,_DIFFIO_RX13n) U4.8(D1)
SRAM1_D2: U1.M27(IO,_DIFFIO_RX11p) U4.9(D2)
SRAM1_D3: U1.N28(IO,_DIFFIO_RX11n) U4.10(D3)
SRAM1_D4: U1.T28(IO,_DIFFIO_RX10p) U4.13(D4)
SRAM1_D5: U1.U27(IO,_DIFFIO_RX10n) U4.14(D5)
SRAM1_D6: U1.V28(IO,_DIFFIO_RX8n) U4.15(D6)
SRAM1_D7: U1.V27(IO,_DIFFIO_RX8p) U4.16(D7)
SRAM1_D8: U1.T25(IO,_DIFFIO_TX7n) U4.29(D8)
SRAM1_D9: U1.T24(IO,_DIFFIO_TX8n) U4.30(D9)
SRAM1_D10: U1.R26(IO,_CLK3n) U4.31(D10)
SRAM1_D11: U1.P26(IO,_CLK1n) U4.32(D11)
SRAM1_D12: U1.M26(IO,_DIFFIO_RX12n) U4.35(D12)
SRAM1_D13: U1.N25(IO,_DIFFIO_TX14n) U4.36(D13)
SRAM1_D14: U1.M25(IO,_DIFFIO_RX12p) U4.37(D14)
SRAM1_D15: U1.M24(IO,_DIFFIO_TX16p) U4.38(D15)
SRAM1_E: U1.K28(IO,_DIFFIO_RX15n) U4.6(~{E})
SRAM1_LB: U1.K26(IO,_DIFFIO_RX16p) U4.39(~{LB})
SRAM1_OE: U1.L25(IO,_DIFFIO_RX14p) U4.41(~{OE})
SRAM1_UB: U1.K25(IO,_DIFFIO_RX16n) U4.40(~{UB})
SRAM1_W: U1.AA27(IO,_DIFFIO_RX2n) U4.17(~{W})
SW0: HDR2.44 U1.AG18(IO,_DQ6B0/DQ1B0)
SW1: HDR2.46 U1.AF18(IO,_DQS6B/_)
SW2: HDR2.48 U1.AG15(IO,_PLL6_OUT2n)
SW3: HDR2.50 U1.AE14(IO,_CLK6n)
SW4: HDR2.52 U1.AH11(IO,_DQ3B6/DQ0B30)
SW5: HDR2.54 U1.AG11(IO,_DQ3B7/DQ0B31)
SW6: HDR2.56 U1.AH10(IO,_DQ3B2/DQ0B26)
SW7: HDR2.58 U1.AG10(IO,_DQS3B/_)
SWC0: HDR2.18 U1.AH25(IO,_DQ9B4/DQ1B28)
SWC1: HDR2.16 U1.AG25(IO,_DQ9B5/DQ1B29)
SWC2: HDR2.14 U1.AH26(IO,_DQ9B6/DQ1B30)
SWC3: HDR2.6 U1.AB28(IO,_DIFFIO_RX0p)
SWR0: HDR2.20 U1.AG24(IO,_DQ9B2/DQ1B26)
SWR1: HDR2.12 U1.AG26(IO,_DQ9B7/DQ1B31)
SWR2: HDR2.10 U1.AF25(IO,_DQ9B3/DQ1B27)
SWR3: HDR2.8 U1.AB27(IO,_DIFFIO_RX0n)
TEMP_ALERT: U1.Y25(IO,_DIFFIO_RX3n) U5.11(ALERT)
TEMPDIODEn: C55.1 R15.2 U1.C14(TEMPDIODEn) U5.4(D-)
TEMPDIODEp: C55.2 U1.B14(TEMPDIODEp) U5.3(D+)
TEST: HDR1.81 U1.B4(IO,_DQ0T4/DQ0T4)
TRST: R6.2 TP5.1 U1.L12(TRST)
VDRIVE: HDR1.20 U1.D20(IO,_DQS7T/DQS1T)
VREF: HDR1.91 R4.1 R5.2
NetC47_1: C47.1 R3.2 U5.2(VDD) U5.15(STBY)
NetHDR1_97: HDR1.97 HDR1.99 TP3.1
NetHDR2_97: HDR2.97 HDR2.99 TP2.1
NetLED1_1: LED1.1(A) R13.2
NetLED1_2: LED1.2(K) U2.4(Y)
NetLED2_1: LED2.1(A) R12.2

Not connected (* = marked no-connect by the designer): U1 AA4(IO,_DIFFIO_RX42p/RUP6)* AA11(IO_(PGM1))* AA14(IO,_PLL6_FBp)* AA15(IO,_PLL6_FBn)* AA18(IO_(CS))* AA19(IO_(RDYnBSY))* AA20(IO)* AB7(IO)* AB10(IO,_FCLK4)* AB11(IO,_RUP7)* AB17(IO,_CLK4n)* AB18(IO)* AB19(IO_(PGM2))* AC8(IO,_FCLK5)* AC9(IO,_DEV_CLRn)* AC10(IO,_RDN7)* AC11(IO_(nRS))* AC13(nCEO) AC19(IO,_FCLK2)* AC21(IO,_FCLK3)* AD8(IO,_DQ2B2/DQ0B18)* AD10(IO,_DQ3B0/DQ0B24)* AE11(IO,_DQ3B5/DQ0B29)* AE19(IO,_DQ6B7/DQ1B7)* AF7(IO,_DQ1B4/DQ0B12)* C7(IO,_DQ1T7/DQ0T15)* C8(IO,_DQ2T1/DQ0T17)* C9(IO,_DQS2T/DQS0T)* C10(IO,_DQ3T2/DQ0T26)* D7(IO,_DQ1T5/DQ0T13)* D9(IO,_DQ2T3/DQ0T19)* D10(IO,_DQS3T/_)* D11(IO,_DQ3T6/DQ0T30)* D15(IO,_PLL5_OUT0n)* E6(IO,_DQ1T0/DQ0T8)* E8(IO,_DQ2T2/DQ0T18)* E10(IO,_DQ3T0/DQ0T24)* E15(IO,_PLL5_OUT0p)* E21(IO,_DQ7T7/DQ1T15)* E23(IO,_DQ8T6/DQ1T22)* F8(IO)* F10(IO,_FCLK7)* F12(IO_(DATA1))* G7(IO)* G10(IO,_FCLK6)* G11(IO,_RDN4)* G18(IO_(DATA7))* G19(IO,_FCLK1)* H11(IO,_RUP4)* H14(IO,_PLL5_FBp)* H15(IO,_PLL5_FBn)* H17(IO_(DATA4))* H18(IO_(DATA6))* J9(IO)* J11(IO,_DEV_OE)* J12(IO_(DATA2))* J13(IO,_CLK12n)* J16(IO,_PLL5_OUT3n) J17(IO,_CLK14n)* J18(IO,_RUP3)* J19(IO_(CLKUSR))* K7(IO,_DIFFIO_TX22n)* K8(IO,_DIFFIO_TX22p)* K11(IO_(nWS))* K14(IO,_PLL5_OUT1p)* K15(IO,_PLL5_OUT1n)* K16(IO,_PLL5_OUT3p) K18(IO_(DATA5))* K19(IO,_RDN3)* K21(IO,_DIFFIO_TX21p)* K22(IO,_DIFFIO_TX21n)* L5(IO,_DIFFIO_TX24n)* L6(IO,_DIFFIO_TX24p)* L7(IO,_DIFFIO_TX23p)* L8(IO,_DIFFIO_TX23n)* L9(IO,_DIFFIO_TX25p)* L10(IO,_DIFFIO_TX25n)* L11(IO)* L13(IO,_CLK13n)* L17(IO,_CLK15n)* L18(IO)* L19(IO,_DIFFIO_TX18n)* L20(IO,_DIFFIO_TX18p)* L21(IO,_DIFFIO_TX20n)* L22(IO,_DIFFIO_TX20p)* L23(IO,_DIFFIO_TX19p)* L24(IO,_DIFFIO_TX19n)* M5(IO,_DIFFIO_TX27p)* M6(IO,_DIFFIO_TX27n)* M7(IO,_DIFFIO_TX26p)* M8(IO,_DIFFIO_TX26n)* M9(IO,_DIFFIO_TX28p)* M10(IO,_DIFFIO_TX28n)* M11(IO)* M12(IO_(DATA3))* M18(IO)* M19(IO,_DIFFIO_TX15n)* M20(IO,_DIFFIO_TX15p)* M21(IO,_DIFFIO_TX17n)* M22(IO,_DIFFIO_TX17p)* M23(IO,_DIFFIO_TX16n)* N5(IO,_DIFFIO_TX31n)* N6(IO,_DIFFIO_TX31p)* N7(IO,_DIFFIO_TX30n)* N8(IO,_DIFFIO_TX30p)* N9(IO,_DIFFIO_TX32p)* N10(IO,_DIFFIO_TX32n)* N19(IO,_DIFFIO_TX11n)* N20(IO,_DIFFIO_TX11p)* N21(IO,_DIFFIO_TX12n)* N22(IO,_DIFFIO_TX12p)* N23(IO,_DIFFIO_TX13n)* N24(IO,_DIFFIO_TX13p)* N26(IO,_DIFFIO_TX14p)* T5(IO,_DIFFIO_TX36p)* T6(IO,_DIFFIO_TX36n)* T7(IO,_DIFFIO_TX34n)* T8(IO,_DIFFIO_TX34p)* T9(IO,_DIFFIO_TX35p)* T10(IO,_DIFFIO_TX35n)* T19(IO,_DIFFIO_TX9p)* T20(IO,_DIFFIO_TX9n)* T21(IO,_DIFFIO_TX10p)* T22(IO,_DIFFIO_TX10n)* T23(IO,_DIFFIO_TX8p)* U5(IO,_DIFFIO_TX38p)* U7(IO,_DIFFIO_TX39n)* U8(IO,_DIFFIO_TX39p)* U9(IO,_DIFFIO_TX37n)* U10(IO,_DIFFIO_TX37p)* U19(IO,_DIFFIO_TX6p)* U20(IO,_DIFFIO_TX6n)* U21(IO,_DIFFIO_TX4p)* U22(IO,_DIFFIO_TX4n)* U24(IO,_DIFFIO_TX5p)* U25(IO,_DIFFIO_RX9n)* V7(IO,_DIFFIO_TX42p)* V8(IO,_DIFFIO_TX42n)* V9(IO,_DIFFIO_TX40n)* V10(IO,_DIFFIO_TX40p)* V11(IO)* V18(IO)* V19(IO,_DIFFIO_TX3p)* V20(IO,_DIFFIO_TX3n)* V21(IO,_DIFFIO_TX1n)* V22(IO,_DIFFIO_TX1p)* W3(IO,_DIFFIO_RX38p)* W5(IO,_DIFFIO_TX43n)* W10(IO_(RUnLU))* W12(IO_(PGM0))* W14(IO,_PLL6_OUT1p)* W15(IO,_PLL6_OUT1n)* W16(IO,_PLL6_OUT3p)* W18(IO)* W19(IO,_RUP8)* W23(IO,_DIFFIO_TX0p)* W25(IO,_DIFFIO_RX5n)* Y9(IO)* Y11(IO)* Y13(IO,_CLK7n)* Y16(IO,_PLL6_OUT3n)* Y17(IO,_CLK5n)* Y18(IO_(nCS))* Y19(IO,_RDN8)*; U2 1(NC); U5 1(NC) 5(NC) 9(NC) 13(NC) 16(NC)

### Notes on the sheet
- ID = 4
- (near HDR1) FPGA_INSTALLED
- (near HDR1) FPGA_ID3
- (near HDR1) FPGA_ID2
- (near HDR1) FPGA_ID1
- (near HDR1) FPGA_ID0
- nIO_PULLUP = Enable weak pullups during configuration
  PORSEL = Power On Delay of 2ms
  VCCSEL = Use 3.3V Logic
  PLL_ENA = PLL always enabled
- (near TP3) 5V from Motherboard (Not used)
- (near R3) FPGA On-Chip-Temperature Sensor
- (near R3) I2C-Addr = 0x30/31
- VCCINT = 1V5
- Schematic is shown for an EP1S10F780I7.  The following alternative devices may be fitted :-
  EP1S10F780xx
  EP1S20F780xx
  EP1S25F780xx
  EP1S40F780xx
- (near U1) PCB Routing
  ----------------------
  VCC_PLL5_OUTA -> VCCIO of bank 9
  VCC_PLL5_OUTB -> VCCIO of bank10
  VCC_PLL6_OUTA -> VCCIO of bank 11
  VCC_PLL6_OUTB -> VCCIO of bank 12
- PLL VCC Decoupling
- (near TP2) 5V from Motherboard (Not used)
- VCC Internal Decoupling
- 3V3 VCC I/O Decoupling

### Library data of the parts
C1-C12 = CAP_POLAR: Polar Capacitor
C13-C55 = CAP: Capacitor
HDR1 = 54075-1009-HD1: Board-to-Board, Docking Station, 0.80mm (.031") Pitch, Shielded Receptacle, Vertical, Ultra Low Profile, SMT; Manufacturer: Molex; Package Information: Latest Revision: Jun-2001; Mating Height: 8.5mm; Voltage: 100V; Current: 0.5A; Contact Resistance: 40mOhm max; PCB Layout: Complies with Manufacturer's Recommendation.
HDR2 = 54075-1009-HD2: Board-to-Board, Docking Station, 0.80mm (.031") Pitch, Shielded Receptacle, Vertical, Ultra Low Profile, SMT; Manufacturer: Molex; Package Information: Latest Revision: Jun-2001; Mating Height: 8.5mm; Voltage: 100V; Current: 0.5A; Contact Resistance: 40mOhm max; PCB Layout: Complies with Manufacturer's Recommendation.
L1-L4 = Inductor: Ferrite Bead; Value: 10mH
LED1 LED2 = HSMX-C670: Typical RED GaAs SMD LED Agilent make; Manufacturer: Generic Components; Class I: Optoelectronic; Fitted: True
R1-R15 = RES: Resistor
U1 = EP1S10F780I7: Stratix 1.5V FPGA, 426 I/Os, 780-Pin FineLine BGA, Speed Grade 7, Industrial Grade; Package Information: Latest Revision: ver11.0, Feb-2003; DQS signal pins: Banks 3, 4, 7 & 8 named according to DQ bus modes. A "/" separates each mode. ie. Mode x8 / Mode x32.; Code - JEDEC: MS-034-AAM-1
U2 = SN74AHC1G04DBVR: Manufacturer: TI; Fitted: True
U3 U4 = SRAM 512Kx16 TSOP44: 512Kx16Bit SRAM TSOP44
U5 = MAX1617DBR2: SMBus Temperature Sensor with Internal and External Diode Input; Package Information: Latest Revision: Feb-2000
